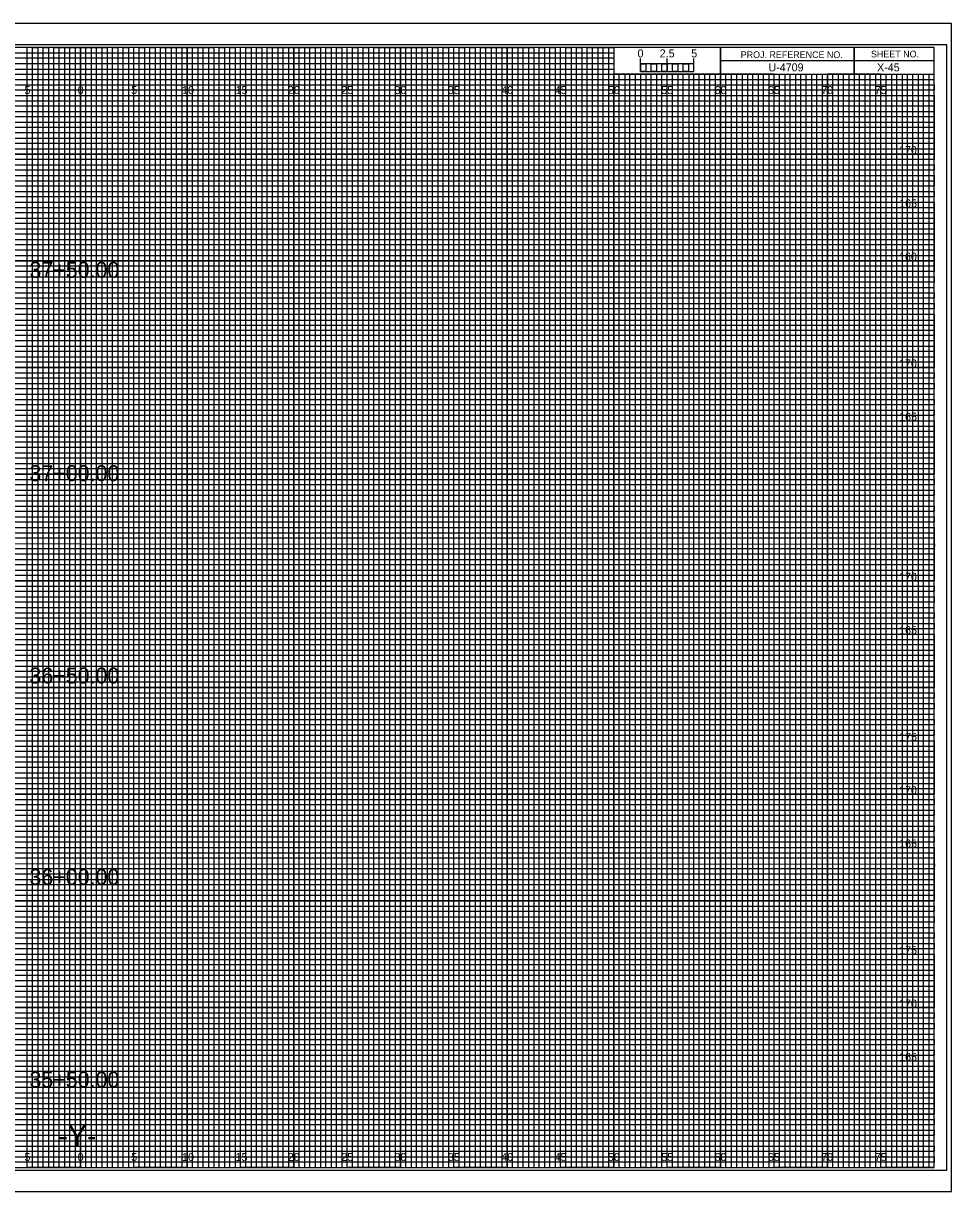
# Model space of a CAD drawing. Extents: x -7 to 162, y 1538 to 1647.
# Drawn here: x 74.6 to 161.7, y 1537.8 to 1647.2 of the extents above; entities that cross this region are included whole.
import ezdxf

# ---------------------------------------------------------------- set-up
doc = ezdxf.new("R2010")
doc.units = 0
for name, color, linetype in [('Prop CMT Pvmt Surface Shoulder', 7, 'Continuous'), ('Prop CMT Shld Paved Course 1', 7, 'Continuous'), ('Prop CMT Shld Paved Course 2', 7, 'Continuous'), ('Prop CMT Shld Paved Course 3', 7, 'Continuous'), ('Prop XS Alignment Label', 7, 'Continuous'), ('Prop XS Bar Scale Labels', 7, 'Continuous'), ('Prop XS Ditch Standard Text', 7, 'Continuous'), ('Prop XS Elevation Labels', 7, 'Continuous'), ('Prop XS Finish Grade CurbGutter', 7, 'Continuous'), ('Prop XS Project Number', 7, 'Continuous'), ('Prop XS Sheet Number', 7, 'Continuous'), ('Prop XS Station Labels', 7, 'Continuous'), ('Sheet Cross Section Scale CELL', 7, 'Continuous'), ('Sheet Cutting Line CELL', 7, 'Continuous'), ('Sheet DOT Grid CELL', 7, 'Continuous'), ('Sheet Plot Border Inside CELL', 7, 'Continuous'), ('Sheet Plot Border Outside CELL', 7, 'Continuous')]:
    doc.layers.add(name, color=color, linetype=linetype)

msp = doc.modelspace()

# ---------------------------------------------------------------- linework, layer by layer
at = {"layer": 'Prop CMT Pvmt Surface Shoulder'}
for p, q in [((0, 1644.5), (130, 1644.5)), ((130, 1643.99), (0, 1643.99)), ((130, 1644.5), (130, 1643.99)), ((0, 1643.5), (130, 1643.5)), ((130, 1642.94), (0, 1642.94)), ((130, 1643.5), (130, 1642.94)), ((0, 1642), (160, 1642))]:
    msp.add_line(p, q, dxfattribs=at)
for points in [[(0, 1641.5), (135, 1641.5), (160, 1641.5), (160, 1641), (0, 1641)], [(0, 1640.5), (160, 1640.5), (160, 1639.5), (0, 1639.5)], [(0, 1639), (160, 1639), (160, 1638.5), (0, 1638.49)], [(0, 1638), (160, 1638), (160, 1637), (0, 1637)], [(0, 1636.5), (160, 1636.5), (160, 1636), (0, 1636)], [(0, 1635.5), (160, 1635.5), (160, 1634.5), (0, 1634.5)], [(0, 1634), (160, 1634), (160, 1633.5), (0, 1633.5)], [(0, 1633), (160, 1633), (160, 1632), (0, 1632)], [(0, 1631.5), (160, 1631.5), (160, 1631), (0, 1631)], [(0, 1630.5), (160, 1630.5), (160, 1629.5), (0, 1629.5)], [(0, 1629), (160, 1629), (160, 1628.5), (0, 1628.5)], [(0, 1628), (160, 1628), (160, 1626.98), (160, 1626.5), (160, 1626), (0, 1626)], [(0, 1627), (160, 1627), (160, 1626.5), (0, 1626.5)], [(0, 1625.5), (160, 1625.5), (160, 1624.5), (0, 1624.52)], [(0, 1624.52), (160, 1624.5), (160, 1624), (0, 1624)], [(0, 1623.5), (160, 1623.5), (160, 1623), (0, 1623)], [(0, 1622), (160, 1622), (160, 1621.5), (0, 1621.5)], [(0, 1621), (160, 1621), (160, 1620.5), (0, 1620.5)], [(-0.04, 1619.44), (160, 1619.44), (160, 1618.94), (-0.04, 1618.94)], [(0, 1618.5), (160, 1618.5), (160, 1618), (0, 1618)], [(0, 1617), (160, 1617), (160, 1616.5), (0, 1616.5)], [(0, 1616), (160, 1616), (160, 1615.5), (0, 1615.5)], [(0, 1614.5), (160, 1614.5), (160, 1614), (0, 1614)], [(0, 1613.5), (160, 1613.5), (160, 1613), (0, 1613)], [(0, 1612), (160, 1612), (160, 1611.5), (0, 1611.5)], [(0, 1611), (160, 1611), (160, 1610.5), (0, 1610.5)], [(0, 1609.5), (160, 1609.5), (160, 1608.99), (0, 1609)], [(0, 1608.5), (160, 1608.5), (160, 1608), (0, 1608)], [(0, 1607), (160, 1607), (160, 1606.5), (0, 1606.5)], [(0, 1606), (160, 1606), (160, 1605.5), (0, 1605.5)], [(0, 1604.5), (160, 1604.5), (160, 1604), (0, 1604)], [(0, 1603.5), (160, 1603.5), (160, 1603), (0, 1603)], [(0, 1602), (160, 1602), (160, 1601.5), (0, 1601.5)], [(0, 1601), (160, 1601), (160, 1600.5), (0, 1600.5)], [(0, 1599.5), (160, 1599.5), (160, 1599), (0, 1599)], [(0, 1598.5), (160.03, 1598.45), (160, 1598), (0, 1598)], [(0, 1597), (160, 1597), (160, 1596.5), (0, 1596.5)], [(0, 1596), (160, 1596), (160, 1595.5), (0, 1595.5)], [(0, 1594.5), (160, 1594.5), (160, 1594), (0, 1594)], [(0, 1593.5), (160, 1593.5), (160, 1593), (0, 1593)], [(0, 1592), (160, 1592), (160, 1591.5), (0, 1591.5)], [(0, 1591), (160, 1591), (160, 1590.5), (0, 1590.5)], [(0, 1589.5), (160, 1589.5), (160, 1589), (0, 1589)], [(0, 1588.5), (160, 1588.5), (160, 1588), (0, 1588)], [(0, 1587), (160, 1587), (160, 1586.5), (0, 1586.5)], [(0, 1586), (160, 1586), (160, 1585.5), (0, 1585.5)], [(0, 1584.5), (160, 1584.5), (160, 1584), (0, 1584)], [(0, 1583.5), (160, 1583.5), (160, 1583), (0, 1583)], [(0, 1582), (160, 1582), (160, 1581.5), (0, 1581.5)], [(0, 1581), (160, 1581), (160, 1580.5), (0, 1580.5)], [(0, 1579.5), (160, 1579.5), (160, 1578.99), (0, 1579)], [(0, 1578.5), (160, 1578.5), (160, 1578), (0, 1578)], [(0, 1577), (160, 1577), (160, 1576.5), (0, 1576.5)], [(0, 1576), (160, 1576), (160, 1575.5), (0, 1575.5)], [(0, 1574.5), (160, 1574.5), (160, 1574), (0, 1574)], [(0, 1573.5), (160, 1573.5), (160, 1573), (0, 1573)], [(0, 1572), (160, 1572), (160, 1571.5), (0, 1571.5)], [(0, 1571), (160, 1571), (160, 1570.5), (0, 1570.5)], [(0, 1569.5), (160, 1569.5), (160, 1569), (0, 1569)], [(0, 1568.5), (160.03, 1568.45), (160, 1568), (0, 1568)], [(0, 1567), (160, 1567), (160, 1566.5), (0, 1566.5)], [(0, 1566), (160, 1566), (160, 1565.5), (0, 1565.5)], [(0, 1564.5), (160, 1564.5), (160, 1564), (0, 1564)], [(0, 1563.5), (160, 1563.5), (160, 1563), (0, 1563)], [(0, 1562), (160, 1562), (160, 1561.5), (0, 1561.5)], [(0, 1561), (160, 1561), (160, 1560.5), (0, 1560.5)], [(0, 1559.5), (160, 1559.5), (160, 1559), (0, 1559)], [(0, 1558.5), (160, 1558.5), (160, 1558), (0, 1558)], [(0, 1557), (160, 1557), (160, 1556.5), (0, 1556.5)], [(0, 1556), (160, 1556), (160, 1555.5), (0, 1555.5)], [(0, 1554.5), (160, 1554.5), (160, 1554), (0, 1554)], [(0, 1553.5), (160, 1553.5), (160, 1553), (0, 1553)], [(0, 1552), (160, 1552), (160, 1551.5), (0, 1551.5)], [(0, 1551), (160, 1551), (160, 1550.5), (0, 1550.5)], [(0, 1549.5), (160, 1549.5), (160, 1549), (0, 1549)], [(0, 1548.5), (160, 1548.5), (160, 1548), (0, 1548)], [(0, 1547), (160, 1547), (160, 1546.5), (0, 1546.5)], [(0, 1546), (160, 1546), (160, 1545.5), (0, 1545.5)], [(0, 1544.5), (160, 1544.5), (160, 1544), (0, 1544)], [(0, 1543.5), (160, 1543.5), (160, 1543), (0, 1543)], [(0, 1542), (160, 1542), (160, 1541.5), (0, 1541.5)], [(0, 1541), (160, 1541), (160, 1540.5), (0, 1540.5)]]:
    msp.add_lwpolyline(points, dxfattribs=at)
at = {"layer": 'Prop CMT Shld Paved Course 2'}
for p, q in [((75, 1645), (70, 1645)), ((75, 1540), (75, 1645)), ((85, 1645), (80, 1645)), ((80, 1645), (80, 1540)), ((85, 1540), (85, 1645)), ((95, 1645), (90, 1645)), ((90, 1645), (90, 1540)), ((95, 1540), (95, 1645)), ((105, 1645), (100, 1645)), ((100, 1645), (100, 1540)), ((105, 1540), (105, 1645)), ((115, 1645), (110, 1645)), ((110, 1645), (110, 1540)), ((115, 1540), (115, 1645)), ((125, 1645), (120, 1645)), ((120, 1645), (120, 1540)), ((125, 1540), (125, 1645)), ((130, 1645), (130, 1540)), ((135, 1540), (135, 1642.5)), ((145, 1642.5), (140, 1642.5)), ((140, 1642.5), (140, 1540)), ((145, 1540), (145, 1642.5)), ((155, 1642.5), (150, 1642.5)), ((150, 1642.5), (150, 1540)), ((155, 1540), (155, 1642.5)), ((80, 1540), (75, 1540)), ((90, 1540), (85, 1540)), ((100, 1540), (95, 1540)), ((110, 1540), (105, 1540)), ((120, 1540), (115, 1540)), ((130, 1540), (125, 1540)), ((140, 1540), (135, 1540)), ((150, 1540), (145, 1540)), ((160, 1540), (155, 1540)), ((160, 1540), (160, 1540))]:
    msp.add_line(p, q, dxfattribs=at)
for points in [[(0, 1640), (160, 1640), (160, 1635), (0, 1635)], [(0, 1630), (160, 1630), (160, 1625), (0, 1625)], [(0, 1620), (160, 1620), (160, 1615), (0, 1615)], [(0, 1610), (160, 1610), (160, 1605), (0, 1605)], [(0, 1600), (160, 1600), (160, 1595), (0, 1595)], [(0, 1590), (160, 1590), (160, 1585), (0, 1585)], [(0, 1580), (160, 1580), (160, 1575), (0, 1575)], [(0, 1570), (160, 1570), (160, 1565), (0, 1565)], [(0, 1560), (160, 1560), (160, 1555), (0, 1555)], [(0, 1550), (160, 1550), (160, 1545), (0, 1545)]]:
    msp.add_lwpolyline(points, dxfattribs=at)
at = {"layer": 'Prop CMT Shld Paved Course 3'}
for points in [[(72.5, 1540), (77.5, 1540), (77.5, 1645), (82.5, 1645), (82.5, 1540), (87.5, 1540), (87.5, 1645), (92.5, 1645), (92.5, 1540), (97.5, 1540), (97.5, 1645), (102.5, 1645), (102.5, 1540), (107.5, 1540), (107.5, 1645), (112.5, 1645), (112.5, 1540), (117.5, 1540), (117.5, 1645), (122.5, 1645), (122.5, 1540), (127.5, 1540), (127.5, 1645), (129.97, 1645), (130, 1645), (130, 1642.5), (132.5, 1642.5), (132.5, 1540), (137.5, 1540), (137.5, 1642.5), (142.5, 1642.5), (142.5, 1540), (147.5, 1540), (147.5, 1642.5), (152.5, 1642.5), (152.5, 1540), (157.5, 1540), (157.5, 1642.5)], [(0, 1642.5), (137.5, 1642.5)], [(0, 1632.5), (160, 1632.5), (160, 1637.5), (0, 1637.5)], [(0, 1622.5), (160, 1622.5), (160, 1627.5), (0, 1627.5)], [(0, 1612.5), (160, 1612.5), (160, 1617.5), (0, 1617.5)], [(0, 1602.5), (160, 1602.5), (160, 1607.5), (0, 1607.5)], [(0, 1592.5), (160, 1592.5), (160, 1597.5), (0, 1597.5)], [(0, 1582.5), (160, 1582.5), (160, 1587.5), (0, 1587.5)], [(0, 1572.5), (160, 1572.5), (160, 1577.5), (0, 1577.5)], [(0, 1562.5), (160, 1562.5), (160, 1567.5), (0, 1567.5)], [(0, 1552.5), (160, 1552.5), (160, 1557.5), (0, 1557.5)], [(0, 1542.5), (160, 1542.5), (160, 1547.5), (0, 1547.5)]]:
    msp.add_lwpolyline(points, dxfattribs=at)
at = {"layer": 'Prop XS Ditch Standard Text'}
for p, q in [((152.5, 1645), (152.5, 1642.5)), ((152.5, 1642.5), (152.5, 1645)), ((160, 1643.75), (140, 1643.75)), ((140, 1643.75), (140, 1642.5)), ((140, 1642.5), (160, 1642.5))]:
    msp.add_line(p, q, dxfattribs=at)
for points in [[(160, 1645), (0, 1645), (0, 1540), (160, 1540)], [(140, 1645), (130, 1645), (130, 1642.52), (140, 1642.52)], [(160, 1645), (140, 1645), (140, 1642.5), (160, 1642.5)]]:
    msp.add_lwpolyline(points, close=True, dxfattribs=at)
at = {"layer": 'Prop XS Finish Grade CurbGutter'}
for p, q in [((133.5, 1642.5), (133, 1642.5)), ((133, 1642.5), (133, 1540)), ((133.5, 1540), (133.5, 1642.5)), ((134.5, 1642.5), (134, 1642.5)), ((134, 1642.5), (134, 1540)), ((134.5, 1540), (134.5, 1642.5)), ((133, 1540), (132.5, 1540)), ((134, 1540), (133.5, 1540))]:
    msp.add_line(p, q, dxfattribs=at)
for points in [[(75, 1540), (75.5, 1540), (75.5, 1645), (76, 1645), (76, 1540)], [(76, 1540), (76.5, 1540), (76.5, 1645), (77, 1645), (77, 1540)], [(77.5, 1540), (78, 1540), (78, 1645), (78.5, 1645), (78.5, 1540)], [(78.5, 1540), (79, 1540), (79, 1645), (79.5, 1645), (79.5, 1540)], [(80, 1540), (80.5, 1540), (80.5, 1645), (81, 1645), (81, 1540)], [(81, 1540), (81.5, 1540), (81.5, 1645), (82, 1645), (82, 1540)], [(82.5, 1540), (83, 1540), (83, 1645), (83.5, 1645), (83.5, 1540)], [(83.5, 1540), (84, 1540), (84, 1645), (84.5, 1645), (84.5, 1540)], [(85, 1540), (85.5, 1540), (85.5, 1645), (86, 1645), (86, 1540)], [(86, 1540), (86.5, 1540), (86.5, 1645), (87, 1645), (87, 1540)], [(87.5, 1540), (88, 1540), (88, 1645), (88.5, 1645), (88.5, 1540)], [(88.5, 1540), (89, 1540), (89, 1645), (89.5, 1645), (89.5, 1540)], [(90, 1540), (90.5, 1540), (90.5, 1645), (91, 1645), (91, 1540)], [(91, 1540), (91.5, 1540), (91.5, 1645), (92, 1645), (92, 1540)], [(92.5, 1540), (93, 1540), (93, 1645), (93.5, 1645), (93.5, 1540)], [(93.5, 1540), (94, 1540), (94, 1645), (94.5, 1645), (94.5, 1540)], [(95, 1540), (95.5, 1540), (95.5, 1645), (96, 1645), (96, 1540)], [(96, 1540), (96.5, 1540), (96.5, 1645), (97, 1645), (97, 1540)], [(97.5, 1540), (98, 1540), (98, 1645), (98.5, 1645), (98.5, 1540)], [(98.5, 1540), (99, 1540), (99, 1645), (99.5, 1645), (99.5, 1540)], [(100, 1540), (100.5, 1540), (100.5, 1645), (101, 1645), (101, 1540)], [(101, 1540), (101.5, 1540), (101.5, 1645), (102, 1645), (102, 1540)], [(102.5, 1540), (103, 1540), (103, 1645), (103.5, 1645), (103.5, 1540)], [(103.5, 1540), (104, 1540), (104, 1645), (104.5, 1645), (104.5, 1540)], [(105, 1540), (105.5, 1540), (105.5, 1645), (106, 1645), (106, 1540)], [(106, 1540), (106.5, 1540), (106.5, 1645), (107, 1645), (107, 1540)], [(107.5, 1540), (108, 1540), (108, 1645), (108.5, 1645), (108.5, 1540)], [(108.5, 1540), (109, 1540), (109, 1645), (109.5, 1645), (109.5, 1540)], [(110, 1540), (110.5, 1540), (110.5, 1645), (111, 1645), (111, 1540)], [(111, 1540), (111.5, 1540), (111.5, 1645), (112, 1645), (112, 1540)], [(112.5, 1540), (113, 1540), (113, 1645), (113.5, 1645), (113.5, 1540)], [(113.5, 1540), (114, 1540), (114, 1645), (114.5, 1645), (114.5, 1540)], [(115, 1540), (115.5, 1540), (115.5, 1645), (116, 1645), (116, 1540)], [(116, 1540), (116.5, 1540), (116.5, 1645), (117, 1645), (117, 1540)], [(117.5, 1540), (118, 1540), (118, 1645), (118.5, 1645), (118.5, 1540)], [(118.5, 1540), (119, 1540), (119, 1645), (119.5, 1645), (119.5, 1540)], [(120, 1540), (120.5, 1540), (120.5, 1645), (121, 1645), (121, 1540)], [(121, 1540), (121.5, 1540), (121.5, 1645), (122, 1645), (122, 1540)], [(122.5, 1540), (123, 1540), (123, 1645), (123.5, 1645), (123.5, 1540)], [(123.5, 1540), (124, 1540), (124, 1645), (124.5, 1645), (124.5, 1540)], [(125, 1540), (125.5, 1540), (125.5, 1645), (126, 1645), (126, 1540)], [(126, 1540), (126.5, 1540), (126.5, 1645), (127, 1645), (127, 1540)], [(127.5, 1540), (128, 1540), (128, 1645), (128.5, 1645), (128.5, 1540)], [(128.5, 1540), (129, 1540), (129, 1645), (129.5, 1645), (129.5, 1540)], [(130, 1540), (130.5, 1540), (130.5, 1642.5), (131.01, 1642.5), (131.01, 1540)], [(131, 1540), (131.5, 1540), (131.5, 1642.5), (132, 1642.5), (132, 1540)], [(135, 1540), (135.49, 1540), (135.49, 1642.5), (136, 1642.5), (136, 1540)], [(136, 1540), (136.5, 1540), (136.5, 1642.5), (137.03, 1642.5), (137.03, 1540)], [(137.5, 1540), (138, 1540), (138, 1642.5), (138.5, 1642.5), (138.5, 1540)], [(138.5, 1540), (139, 1540), (139, 1642.5), (139.5, 1642.5), (139.5, 1540)], [(140, 1540), (140.5, 1540), (140.5, 1642.5), (141, 1642.5), (141, 1540)], [(141, 1540), (141.5, 1540), (141.5, 1642.5), (142, 1642.5), (142, 1540)], [(142.5, 1540), (143, 1540), (143, 1642.5), (143.5, 1642.5), (143.5, 1540)], [(143.5, 1540), (144, 1540), (144, 1642.5), (144.5, 1642.5), (144.5, 1540)], [(145, 1540), (145.5, 1540), (145.5, 1642.5), (146, 1642.5), (146, 1540)], [(146, 1540), (146.5, 1540), (146.5, 1642.5), (147, 1642.5), (147, 1540)], [(147.5, 1540), (148, 1540), (148, 1642.5), (148.5, 1642.5), (148.5, 1540)], [(148.5, 1540), (149, 1540), (149, 1642.5), (149.5, 1642.5), (149.5, 1540)], [(150, 1540), (150.5, 1540), (150.5, 1642.5), (151, 1642.5), (151, 1540)], [(151, 1540), (151.5, 1540), (151.5, 1642.5), (152, 1642.5), (152, 1540)], [(152.5, 1540), (153, 1540), (153, 1642.5), (153.5, 1642.5), (153.5, 1540)], [(153.5, 1540), (154, 1540), (154, 1642.5), (154.5, 1642.5), (154.5, 1540)], [(155, 1540), (155.5, 1540), (155.5, 1642.5), (156, 1642.5), (156, 1540)], [(156, 1540), (156.5, 1540), (156.5, 1642.5), (157, 1642.5), (157, 1540)], [(157.5, 1540), (158, 1540), (158, 1642.5), (158.5, 1642.5), (158.5, 1540)], [(158.5, 1540), (159, 1540), (159, 1642.5), (159.5, 1642.5), (159.5, 1540)]]:
    msp.add_lwpolyline(points, dxfattribs=at)
at = {"layer": 'Sheet Cross Section Scale CELL'}
for p, q in [((132.5, 1642.75), (132.5, 1643.95)), ((132.5, 1643.45), (132.5, 1643.95)), ((135, 1642.75), (135, 1643.95)), ((137.5, 1642.75), (137.5, 1643.95)), ((137.5, 1643.45), (137.5, 1643.95))]:
    msp.add_line(p, q, dxfattribs=at)
for points in [[(137.5, 1643.45), (132.5, 1643.45), (132.5, 1642.75), (137.5, 1642.75)], [(132.5, 1643.45), (133, 1643.45), (133, 1642.75), (132.5, 1642.75)], [(133.5, 1643.45), (134, 1643.45), (134, 1642.75), (133.5, 1642.75)], [(134.5, 1643.45), (135, 1643.45), (135, 1642.75), (134.5, 1642.75)], [(135.5, 1643.45), (136, 1643.45), (136, 1642.75), (135.5, 1642.75)], [(136.5, 1643.45), (137, 1643.45), (137, 1642.75), (136.5, 1642.75)]]:
    msp.add_lwpolyline(points, close=True, dxfattribs=at)
at = {"layer": 'Sheet Cutting Line CELL'}
for p, q in [((161.65, 1647.25), (-6.7, 1647.25)), ((-6.7, 1537.75), (161.65, 1537.75))]:
    msp.add_line(p, q, dxfattribs=at)
at = {"layer": 'Sheet DOT Grid CELL'}
for p, q in [((75, 1540), (75, 1645)), ((80, 1540), (80, 1645)), ((85, 1540), (85, 1645)), ((90, 1540), (90, 1645)), ((95, 1540), (95, 1645)), ((100, 1540), (100, 1645)), ((105, 1540), (105, 1645)), ((110, 1540), (110, 1645)), ((115, 1540), (115, 1645)), ((120, 1540), (120, 1645)), ((125, 1540), (125, 1645)), ((130, 1540), (130, 1642.34)), ((135, 1540), (135, 1642.34)), ((140, 1540), (140, 1642.34)), ((145, 1540), (145, 1642.34)), ((150, 1540), (150, 1642.34)), ((155, 1540), (155, 1642.34)), ((0, 1640), (160, 1640)), ((0, 1635), (160, 1635)), ((0, 1630), (160, 1630)), ((0, 1625), (160, 1625)), ((0, 1620), (160, 1620)), ((0, 1615), (160, 1615)), ((0, 1610), (160, 1610)), ((0, 1605), (160, 1605)), ((0, 1600), (160, 1600)), ((0, 1595), (160, 1595)), ((0, 1590), (160, 1590)), ((0, 1585), (160, 1585)), ((0, 1580), (160, 1580)), ((0, 1575), (160, 1575)), ((0, 1570), (160, 1570)), ((0, 1565), (160, 1565)), ((0, 1560), (160, 1560)), ((0, 1555), (160, 1555)), ((0, 1550), (160, 1550)), ((0, 1545), (160, 1545))]:
    msp.add_line(p, q, dxfattribs=at)
at = {"layer": 'Sheet Plot Border Inside CELL'}
msp.add_lwpolyline([(-5.4, 1539.75), (161.2, 1539.75), (161.2, 1645.25), (-5.4, 1645.25)], close=True, dxfattribs=at)
at = {"layer": 'Sheet Plot Border Outside CELL'}
msp.add_lwpolyline([(-6.7, 1537.75), (161.65, 1537.75), (161.65, 1647.25), (-6.7, 1647.25)], close=True, dxfattribs=at)

# ---------------------------------------------------------------- texts
at = {"layer": 'Prop CMT Shld Paved Course 1'}
for s, p in [('5', (74.74, 1640.62)), ('0', (79.73, 1640.62)), ('0', (79.73, 1640.62)), ('5', (84.74, 1640.62)), ('10', (89.52, 1640.62)), ('15', (94.53, 1640.62)), ('20', (99.43, 1640.62)), ('25', (104.44, 1640.62)), ('30', (109.43, 1640.62)), ('35', (114.44, 1640.62)), ('40', (119.43, 1640.62)), ('45', (124.44, 1640.62)), ('50', (129.43, 1640.62)), ('55', (134.44, 1640.62)), ('60', (139.43, 1640.62)), ('65', (144.44, 1640.62)), ('70', (149.43, 1640.62)), ('75', (154.44, 1640.62)), ('5', (74.74, 1540.62)), ('0', (79.73, 1540.62)), ('0', (79.73, 1540.62)), ('5', (84.74, 1540.62)), ('10', (89.52, 1540.62)), ('15', (94.53, 1540.62)), ('20', (99.43, 1540.62)), ('25', (104.44, 1540.62)), ('30', (109.43, 1540.62)), ('35', (114.44, 1540.62)), ('40', (119.43, 1540.62)), ('45', (124.44, 1540.62)), ('50', (129.43, 1540.62)), ('55', (134.44, 1540.62)), ('60', (139.43, 1540.62)), ('65', (144.44, 1540.62)), ('70', (149.43, 1540.62)), ('75', (154.44, 1540.62))]:
    msp.add_text(s, height=0.75, dxfattribs=at).set_placement(p)
at = {"layer": 'Prop XS Alignment Label'}
msp.add_text('-Y-', height=2, dxfattribs=at).set_placement((77.92, 1542))
at = {"layer": 'Prop XS Bar Scale Labels'}
for s, p in [('2.5', (134.29, 1644.06)), ('5', (137.24, 1644.06))]:
    msp.add_text(s, height=0.75, dxfattribs=at).set_placement(p)
at = {"layer": 'Prop XS Ditch Standard Text'}
for s, p in [('SHEET NO.', (154.09, 1644.06)), ('PROJ. REFERENCE NO.', (141.88, 1644))]:
    msp.add_text(s, height=0.625, dxfattribs=at).set_placement(p)
at = {"layer": 'Prop XS Elevation Labels'}
for s, p in [('170', (156.72, 1635)), ('165', (156.73, 1630)), ('160', (156.72, 1625)), ('170', (156.72, 1615)), ('165', (156.73, 1610)), ('170', (156.72, 1595)), ('165', (156.73, 1590)), ('175', (156.73, 1580)), ('170', (156.72, 1575)), ('165', (156.73, 1570)), ('175', (156.73, 1560)), ('170', (156.72, 1555)), ('165', (156.73, 1550))]:
    msp.add_text(s, height=0.75, dxfattribs=at).set_placement(p)
at = {"layer": 'Prop XS Project Number'}
msp.add_text('U-4709', height=0.75, dxfattribs=at).set_placement((144.48, 1642.75))
at = {"layer": 'Prop XS Sheet Number'}
msp.add_text('X-45', height=0.75, dxfattribs=at).set_placement((154.66, 1642.75))
at = {"layer": 'Prop XS Station Labels'}
for s, p in [('37+50.00', (75.21, 1623.4)), ('37+00.00', (75.21, 1604.34)), ('36+50.00', (75.21, 1585.37)), ('36+00.00', (75.21, 1566.5)), ('35+50.00', (75.21, 1547.5))]:
    msp.add_text(s, height=1.5, dxfattribs=at).set_placement(p)
at = {"layer": 'Sheet Cross Section Scale CELL'}
msp.add_text('0', height=0.75, dxfattribs=at).set_placement((132.21, 1644.06))

doc.saveas('drawing.dxf')
